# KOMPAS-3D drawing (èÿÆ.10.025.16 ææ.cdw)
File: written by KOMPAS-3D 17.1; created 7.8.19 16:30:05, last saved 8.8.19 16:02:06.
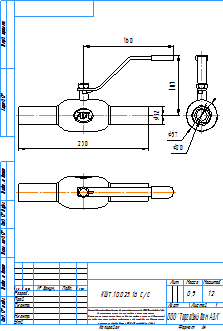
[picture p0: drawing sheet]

Sheet 1: A4, portrait

Title block, sheet 1: name: КШТ.10.025.16 С/С; material: Сталь 20  ГОСТ 1050-2013; mass: 0,9; sheets: 1; sheet format: A4; stored path: C:\Users\kka\KOMPAS_Work\Модели кранов для исследований\DN65\КШТ.10.065.16 СС.cdw

Views: Вид 1, Проекционный вид 2, Проекционный вид 3
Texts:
  kka
  adl
  Рама для чертежей
  Лит-Масса-Масштаб
  Материал-Предприятие
  Масштаб
  Изм.
  Лист
  № докум.
  Подп.
  Дата
  Лит.
  Разраб.
  Пров.
  Т.контр.
  Листов
  Внимание! Данный продукт является объектом авторского права ООО «Торговый Дом АДЛ».
  Запрещается изменение, копирование, распространение
  (в том числе путем копирования на другие сайты и ресурсы в Интернете)
  или любое иное использование информации и объектов без предварительного
  согласия правообладателя (ООО «Торговый Дом АДЛ»).
  Н.контр.
  Утв.
  ООО "Торговый дом АДЛ"
  Изменение
  Номер документа
  Подпись
  Обозначение документа
  Наименование изделия
  Масса изделия по ГОСТ 2.109-73
  Порядковый номер листа
  Общее количество листов в документе
  Характер работы, выполненной лицом, подписавшим документ
  Наименование или индекс предприятия, выпускающего документ
  Инв. № подл.
  Подп. и дата
  Взам. инв. №
  Инв. № дубл.
  Инвентарный номер подлинника по ГОСТ 2.501-68
  Подпись принявшего подлинник в отдел технической документации
  Инвентарный номер подлинника, взамен которого выпущен данный подлинник
  Инвентарный номер дубликата по ГОСТ 2.502-68
  Подпись принявшего дубликат в отдел технической документации
  Справ. №
  Перв. примен.
  Обозначение документа, взамен или на основании которого выпущен данный документ
  Обозначение документа, в котором впервые записан данный документ
  Подпись лица, копировавшего чертеж
  Обозначение формата листа
  !Рама для чертежа
Dimensions and other numbers on the sheet: 230; 32; 160; 107; 57; 20; 1:2; 1; 0,9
